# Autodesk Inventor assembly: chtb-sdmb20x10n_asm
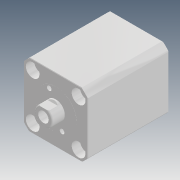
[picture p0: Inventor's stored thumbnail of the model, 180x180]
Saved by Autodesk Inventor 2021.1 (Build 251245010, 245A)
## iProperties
Company: Microsoft
Created: 2018-05
Part Number: chtb-sdmb20x10n_asm
Description: STEP AP214
Document SubType Name: Assembly
Designer: user
Title: chtb-sdmb20x10n_asm.STEP
Author: Windows
Revision Number: ÈÎºÎ
Sending System: SolidWorks 2015
Preprocessor: SwSTEP 2.0
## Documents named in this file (4)
- D:\Vault_2016\Projekty\Clamptek\Hydraulic\CHTB\CHTB-20\Inventor\CHTB-SDMB20x10N\chtb-sdmb20x10n_asm.iam
- D:\Vault_2016\Projekty\Clamptek\Hydraulic\CHTB\CHTB-20\Inventor\CHTB-SDMB20x10N\CHTB-SDMB20X10NBT.ipt
- D:\Vault_2016\Projekty\Clamptek\Hydraulic\CHTB\CHTB-20\Inventor\CHTB-SDMB20x10N\CHTB-SDMB20X10NHSG.ipt
- D:\Vault_2016\Projekty\Clamptek\Hydraulic\CHTB\CHTB-20\Inventor\CHTB-SDMB20x10N\QG_3.ipt
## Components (3 placed, 3 different names)
1. CHTB-SDMB20X10NBT_1
2. CHTB-SDMB20X10NHSG_2
3. QG_3_3
